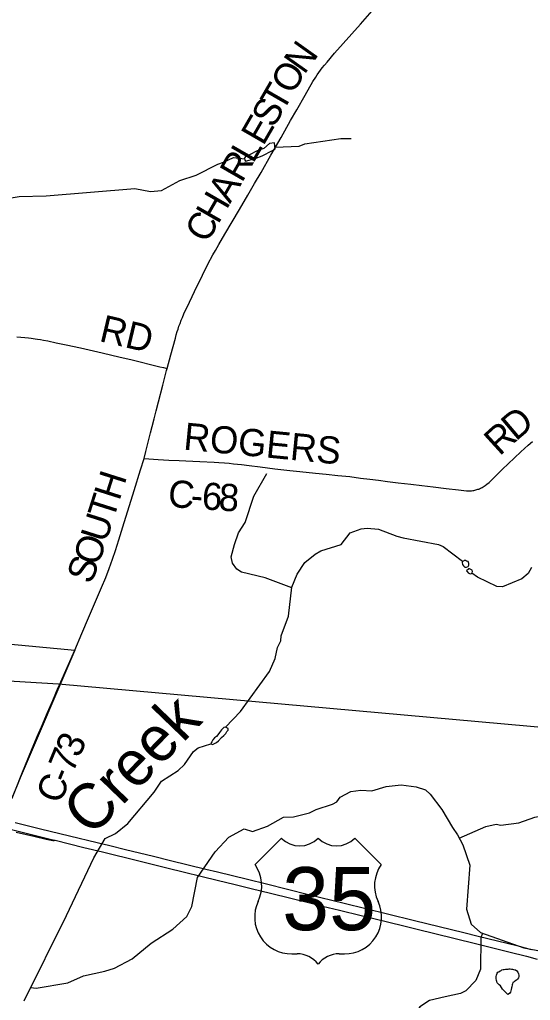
# Model space of a CAD drawing. Extents: x -49 to -8.2, y 9.4 to 23.5.
# Drawn here: x -12.176 to -11.642, y 12.877 to 13.902 of the extents above; entities that cross this region are included whole.
import ezdxf

# ---------------------------------------------------------------- set-up
doc = ezdxf.new("R2010")
doc.units = 0
for name, color, linetype in [('GM_X_Corporation', 7, 'Continuous'), ('GM_X_County_Road', 7, 'Continuous'), ('GM_X_County_Road_Text', 7, 'Continuous'), ('GM_X_Interchange_Ramps', 7, 'Continuous'), ('GM_X_Major_River', 7, 'Continuous'), ('GM_X_Major_River_Text', 7, 'Continuous'), ('GM_X_Minor_Lake', 7, 'Continuous'), ('GM_X_Minor_River', 7, 'Continuous'), ('GM_X_Township', 7, 'Continuous'), ('GM_X_Township_Road', 7, 'Continuous'), ('GM_X_Township_Road_Text', 7, 'Continuous'), ('GM_X_US_Route', 7, 'Continuous'), ('GM_X_US_Shield', 7, 'Continuous')]:
    doc.layers.add(name, color=color, linetype=linetype)

msp = doc.modelspace()

# ---------------------------------------------------------------- linework, layer by layer
at = {"layer": 'GM_X_Corporation'}
msp.add_lwpolyline([(-12.3034, 13.2604), (-12.1182, 13.2429), (-12.1752, 13.1093), (-12.1838, 13.0878)], dxfattribs=at)
at = {"layer": 'GM_X_County_Road'}
for points in [[(-12.0216, 13.5374), (-12.0178, 13.5517), (-12.013, 13.5691), (-12.012, 13.5726), (-12.011, 13.576), (-12.0102, 13.5787), (-12.0092, 13.5816), (-12.0081, 13.5846), (-12.0069, 13.5878), (-12.0056, 13.5909), (-12.0041, 13.5944), (-12.0027, 13.5977), (-12.0007, 13.6017), (-11.9929, 13.618), (-11.9846, 13.635), (-11.9789, 13.6464), (-11.9737, 13.6563), (-11.9711, 13.6608), (-11.9676, 13.6671), (-11.9612, 13.6778), (-11.9536, 13.6906), (-11.9461, 13.7035), (-11.9373, 13.7185), (-11.9302, 13.7309), (-11.9234, 13.7424), (-11.9131, 13.7605), (-11.9025, 13.7791), (-11.8925, 13.7967), (-11.886, 13.808), (-11.8774, 13.8231), (-11.8692, 13.8374), (-11.8663, 13.8422), (-11.8647, 13.8446), (-11.8631, 13.8468), (-11.8613, 13.8492), (-11.8594, 13.8518), (-11.8571, 13.8546), (-11.8544, 13.8578), (-11.8465, 13.867), (-11.8196, 13.8975), (-11.7876, 13.9339)], [(-12.0457, 13.4434), (-12.0439, 13.4505), (-12.0388, 13.4703), (-12.0371, 13.4767), (-12.035, 13.4849), (-12.0329, 13.493), (-12.0305, 13.5025), (-12.0261, 13.52), (-12.0222, 13.5352), (-12.0216, 13.5374)], [(-12.0457, 13.4434), (-12.0308, 13.4423), (-12.0197, 13.4417), (-12.009, 13.4412), (-12.0019, 13.4408), (-11.9875, 13.4402), (-11.9723, 13.4394), (-11.9674, 13.4391), (-11.9615, 13.4387), (-11.9569, 13.4383), (-11.9522, 13.4378), (-11.9439, 13.4369), (-11.9357, 13.436), (-11.9245, 13.4346), (-11.909, 13.4326), (-11.8932, 13.4307), (-11.8828, 13.4296), (-11.8666, 13.4279), (-11.8554, 13.4268), (-11.8433, 13.4256), (-11.8306, 13.4243), (-11.8193, 13.4229), (-11.8098, 13.4218), (-11.8007, 13.4206), (-11.7912, 13.4194), (-11.7802, 13.418), (-11.7668, 13.4164), (-11.7555, 13.4151), (-11.7436, 13.4136), (-11.73, 13.412), (-11.7169, 13.4105), (-11.7116, 13.4099), (-11.7086, 13.4095), (-11.7062, 13.4094), (-11.7047, 13.4095), (-11.7035, 13.4096), (-11.7021, 13.4098), (-11.7009, 13.41), (-11.6989, 13.4105), (-11.6978, 13.4108), (-11.6967, 13.4111), (-11.6958, 13.4114), (-11.6951, 13.4117), (-11.694, 13.4122), (-11.6931, 13.4126), (-11.6922, 13.4131), (-11.6912, 13.4137), (-11.6903, 13.4143), (-11.6892, 13.4151), (-11.6874, 13.4164), (-11.685, 13.4183), (-11.6834, 13.4198), (-11.6766, 13.4265), (-11.6711, 13.4321), (-11.6651, 13.4378), (-11.6586, 13.4439), (-11.6519, 13.4502), (-11.6443, 13.4572), (-11.6398, 13.4612)], [(-12.1182, 13.2429), (-12.1109, 13.2603), (-12.1038, 13.2768), (-12.0902, 13.3084), (-12.0857, 13.319), (-12.0821, 13.3283), (-12.0786, 13.338), (-12.0756, 13.3471), (-12.0722, 13.3584), (-12.0679, 13.372), (-12.056, 13.4099), (-12.0494, 13.4313), (-12.0457, 13.4434)], [(-12.1354, 13.2037), (-12.1341, 13.2068), (-12.1182, 13.2429)], [(-12.1411, 13.1904), (-12.1354, 13.2037)], [(-12.1838, 13.0878), (-12.1801, 13.0969), (-12.1735, 13.1137), (-12.1627, 13.1401), (-12.1573, 13.1526), (-12.153, 13.1626), (-12.1465, 13.1777), (-12.1411, 13.1904)]]:
    msp.add_lwpolyline(points, dxfattribs=at)
at = {"layer": 'GM_X_Interchange_Ramps'}
msp.add_lwpolyline([(-12.1795, 13.0525), (-12.161, 13.0483), (-12.1481, 13.0454), (-12.1427, 13.0442), (-12.1411, 13.0439), (-12.1403, 13.0438), (-12.1395, 13.0439), (-12.1386, 13.0441)], dxfattribs=at)
at = {"layer": 'GM_X_Major_River'}
for points in [[(-11.9604, 13.1623), (-11.9449, 13.1787), (-11.9147, 13.2204), (-11.9086, 13.2341), (-11.9063, 13.2455), (-11.9027, 13.2526), (-11.9023, 13.2579), (-11.8947, 13.2785), (-11.8912, 13.3088), (-11.8857, 13.3222), (-11.8775, 13.3344), (-11.8667, 13.3431), (-11.8609, 13.3467), (-11.8396, 13.3533), (-11.8301, 13.3657), (-11.8187, 13.3698), (-11.8126, 13.3706), (-11.8005, 13.3694), (-11.7814, 13.3622), (-11.775, 13.3604), (-11.7381, 13.3532), (-11.7332, 13.3512), (-11.7129, 13.336)], [(-11.7129, 13.336), (-11.7132, 13.3345), (-11.7129, 13.3325), (-11.7118, 13.331), (-11.7105, 13.3298), (-11.7088, 13.3298), (-11.7069, 13.3305), (-11.7061, 13.3318), (-11.7063, 13.3335), (-11.707, 13.3355), (-11.7085, 13.3361), (-11.7096, 13.3365), (-11.711, 13.3365), (-11.7113, 13.3363)], [(-11.7129, 13.336), (-11.7113, 13.3363)], [(-11.7085, 13.3258), (-11.708, 13.325), (-11.7069, 13.3237), (-11.7056, 13.3229), (-11.7044, 13.3227), (-11.7035, 13.323), (-11.7029, 13.3236), (-11.7023, 13.3253), (-11.7026, 13.3266), (-11.7041, 13.3274), (-11.7056, 13.328), (-11.7064, 13.3279)], [(-11.7064, 13.3279), (-11.7085, 13.3258)], [(-11.6407, 13.3294), (-11.6443, 13.3232), (-11.651, 13.3176), (-11.671, 13.3091), (-11.6769, 13.3096), (-11.6973, 13.3193), (-11.703, 13.3235)], [(-11.9604, 13.1623), (-11.9624, 13.1621), (-11.9648, 13.1597), (-11.9669, 13.1569), (-11.9686, 13.1543), (-11.97, 13.1526), (-11.9719, 13.1511), (-11.9739, 13.1491), (-11.975, 13.1472), (-11.9756, 13.1461), (-11.976, 13.1451), (-11.9743, 13.1443), (-11.9701, 13.1465), (-11.968, 13.148), (-11.9649, 13.1516), (-11.9624, 13.1536), (-11.9603, 13.1558), (-11.9591, 13.1577), (-11.9578, 13.1592), (-11.9579, 13.1611)], [(-11.9579, 13.1611), (-11.9604, 13.1623)], [(-12.1711, 12.8763), (-12.1266, 12.9654), (-12.0981, 13.0259), (-12.0862, 13.0458), (-12.0757, 13.0511), (-12.0626, 13.0618), (-12.0353, 13.0943), (-12.0273, 13.1059), (-12.0099, 13.1171), (-12.0035, 13.1235), (-11.994, 13.137), (-11.989, 13.1406), (-11.9758, 13.145)]]:
    msp.add_lwpolyline(points, dxfattribs=at)
at = {"layer": 'GM_X_Minor_Lake'}
for points in [[(-11.9398, 13.7543), (-11.9295, 13.757), (-11.9223, 13.7597), (-11.9116, 13.7652), (-11.9085, 13.7672), (-11.9094, 13.7733), (-11.9147, 13.7727), (-11.9205, 13.7673), (-11.9273, 13.7649), (-11.9355, 13.7609), (-11.9397, 13.7589)], [(-11.9397, 13.7589), (-11.9404, 13.7582), (-11.9407, 13.7571), (-11.9405, 13.7553), (-11.9398, 13.7543)], [(-11.9604, 13.1623), (-11.9449, 13.1787), (-11.9147, 13.2204), (-11.9086, 13.2341), (-11.9063, 13.2455), (-11.9027, 13.2526), (-11.9023, 13.2579), (-11.8947, 13.2785), (-11.8912, 13.3088), (-11.8857, 13.3222), (-11.8775, 13.3344), (-11.8667, 13.3431), (-11.8609, 13.3467), (-11.8396, 13.3533), (-11.8301, 13.3657), (-11.8187, 13.3698), (-11.8126, 13.3706), (-11.8005, 13.3694), (-11.7814, 13.3622), (-11.775, 13.3604), (-11.7381, 13.3532), (-11.7332, 13.3512), (-11.7129, 13.336)], [(-11.6654, 12.883), (-11.6711, 12.8885), (-11.6733, 12.892), (-11.6744, 12.8931), (-11.6754, 12.8939), (-11.6765, 12.8952), (-11.6769, 12.8964), (-11.6772, 12.8973), (-11.6776, 12.8994), (-11.6776, 12.9008), (-11.6776, 12.9017), (-11.6774, 12.903), (-11.6766, 12.9051), (-11.6758, 12.9061), (-11.6749, 12.9066), (-11.6735, 12.9076), (-11.6726, 12.9081), (-11.6716, 12.9085), (-11.6703, 12.9089), (-11.6692, 12.909), (-11.668, 12.9092), (-11.6667, 12.9092), (-11.665, 12.9094), (-11.664, 12.9095), (-11.6629, 12.9095), (-11.6617, 12.9093), (-11.6606, 12.9093), (-11.6597, 12.9091), (-11.6583, 12.9087), (-11.6574, 12.9085), (-11.6561, 12.9076), (-11.655, 12.9062), (-11.6544, 12.9043), (-11.6538, 12.903), (-11.6539, 12.9016), (-11.6544, 12.9003), (-11.6554, 12.8988), (-11.6564, 12.8979), (-11.6581, 12.8967), (-11.659, 12.896), (-11.6602, 12.8954), (-11.6606, 12.8941), (-11.661, 12.8928), (-11.6614, 12.8907), (-11.6616, 12.8898), (-11.662, 12.888), (-11.6624, 12.8867), (-11.6628, 12.8852), (-11.6635, 12.8841), (-11.6647, 12.8831), (-11.6654, 12.883)]]:
    msp.add_lwpolyline(points, dxfattribs=at)
at = {"layer": 'GM_X_Minor_River'}
for points in [[(-11.9087, 13.7687), (-11.8835, 13.77), (-11.8776, 13.7722), (-11.8401, 13.778), (-11.8293, 13.7779)], [(-12.4055, 13.629), (-12.3833, 13.6343), (-12.3324, 13.6596), (-12.3198, 13.6639), (-12.2664, 13.6757), (-12.2323, 13.6945), (-12.2103, 13.7074), (-12.1948, 13.7141), (-12.1764, 13.7174), (-12.1481, 13.718), (-12.0554, 13.7256), (-12.0389, 13.7225), (-12.0273, 13.7236), (-12.0082, 13.7339), (-11.9914, 13.7397), (-11.9685, 13.7512), (-11.9626, 13.7532), (-11.9521, 13.7581), (-11.9407, 13.7568)], [(-11.8913, 13.3082), (-11.9192, 13.3186), (-11.9439, 13.3243), (-11.9488, 13.3277), (-11.9532, 13.3338), (-11.9548, 13.3403), (-11.9513, 13.3532), (-11.9471, 13.3654), (-11.9399, 13.3763), (-11.9311, 13.4039), (-11.9172, 13.4276)], [(-12.1642, 12.8902), (-12.1584, 12.8893), (-12.1255, 12.8951), (-12.1091, 12.9024), (-12.0866, 12.9071), (-12.0765, 12.9102), (-12.0583, 12.9203), (-12.0383, 12.9365), (-12.0157, 12.9512), (-12.0011, 12.9645), (-11.9956, 12.9748), (-11.9898, 13.0051), (-11.9713, 13.0319), (-11.9572, 13.0472), (-11.9409, 13.0559), (-11.9324, 13.0534), (-11.9166, 13.0588), (-11.8999, 13.0684), (-11.8895, 13.0686), (-11.8728, 13.0729), (-11.8659, 13.0763), (-11.8489, 13.0817), (-11.8441, 13.0843), (-11.8406, 13.0892), (-11.8297, 13.0951), (-11.8191, 13.0964), (-11.8077, 13.0958), (-11.7925, 13.1005), (-11.7769, 13.1019), (-11.7613, 13.0999), (-11.7515, 13.0967), (-11.7466, 13.0924), (-11.7346, 13.0764), (-11.7232, 13.0574), (-11.7182, 13.0499), (-11.7125, 13.0392), (-11.7051, 13.018), (-11.7086, 12.9719), (-11.7039, 12.9564), (-11.6942, 12.9477), (-11.6487, 12.9315), (-11.6286, 12.9279)], [(-11.7163, 13.0464), (-11.6885, 13.0585), (-11.6776, 13.061), (-11.6727, 13.0599), (-11.6539, 13.0624), (-11.6371, 13.0682), (-11.6269, 13.0705), (-11.6125, 13.0702), (-11.5974, 13.065), (-11.5923, 13.0649), (-11.5658, 13.0534), (-11.555, 13.0525), (-11.5396, 13.0526), (-11.5347, 13.054), (-11.508, 13.0518)], [(-11.6921, 12.9469), (-11.6936, 12.942), (-11.694, 12.9093), (-11.6989, 12.8976), (-11.7092, 12.8868), (-11.7149, 12.884), (-11.7311, 12.8804), (-11.7474, 12.8765), (-11.7574, 12.87), (-11.7825, 12.8346)]]:
    msp.add_lwpolyline(points, dxfattribs=at)
at = {"layer": 'GM_X_Township'}
for p, q in [((-12.3691, 13.2212), (-12.1351, 13.2078)), ((-12.1351, 13.2078), (-11.3819, 13.1401))]:
    msp.add_line(p, q, dxfattribs=at)
at = {"layer": 'GM_X_Township_Road'}
msp.add_lwpolyline([(-12.1786, 13.5706), (-12.1703, 13.5697), (-12.1666, 13.5693), (-12.1638, 13.569), (-12.1595, 13.5684), (-12.157, 13.568), (-12.1539, 13.5676), (-12.1508, 13.567), (-12.1463, 13.5662), (-12.1374, 13.5643), (-12.1271, 13.5622), (-12.1122, 13.5589), (-12.0895, 13.5537), (-12.0708, 13.5494), (-12.0596, 13.5467), (-12.0292, 13.5393), (-12.0253, 13.5383), (-12.0216, 13.5374)], dxfattribs=at)
at = {"layer": 'GM_X_US_Route'}
for points in [[(-12.1953, 13.058), (-12.1423, 13.045), (-12.1386, 13.0441), (-12.1085, 13.0367), (-12.0892, 13.0319), (-12.0512, 13.0225), (-12.022, 13.0153), (-11.968, 13.0021), (-11.952, 12.9981), (-11.9336, 12.9935), (-11.9137, 12.9887), (-11.8922, 12.9835), (-11.8696, 12.9779), (-11.8591, 12.9753), (-11.8413, 12.9709), (-11.8189, 12.9655), (-11.8084, 12.963), (-11.7728, 12.9542), (-11.7601, 12.951), (-11.7218, 12.9417), (-11.6979, 12.9358), (-11.6645, 12.9276), (-11.6461, 12.9229), (-11.6347, 12.9198)], [(-12.1804, 13.0626), (-12.1719, 13.0606), (-12.154, 13.0561), (-12.1236, 13.0489), (-12.0946, 13.0418), (-12.0816, 13.0386), (-12.065, 13.0346), (-12.0358, 13.0274), (-12.0182, 13.0231), (-11.9811, 13.014), (-11.9691, 13.011), (-11.9377, 13.0033), (-11.9178, 12.9984), (-11.8737, 12.9875), (-11.8366, 12.9785), (-11.7914, 12.9673), (-11.763, 12.9603), (-11.7114, 12.9477), (-11.6963, 12.944), (-11.6562, 12.934), (-11.6412, 12.93)]]:
    msp.add_lwpolyline(points, dxfattribs=at)
at = {"layer": 'GM_X_US_Shield'}
for p, q in [((-11.9022, 13.0462), (-11.9297, 13.0187)), ((-11.7978, 13.0187), (-11.8253, 13.0462)), ((-11.8912, 12.9253), (-11.8857, 12.9253)), ((-11.8418, 12.9253), (-11.8363, 12.9253))]:
    msp.add_line(p, q, dxfattribs=at)
for centre, radius, start, end in [((-11.883, 13.0658), 0.0275, 225.573, 314.427), ((-11.8445, 13.0658), 0.0275, 225.573, 314.427), ((-11.9612, 12.9967), 0.0385, 334.5471, 35.0009), ((-11.7663, 12.9967), 0.0385, 144.9991, 205.4529), ((-11.8916, 12.9638), 0.0385, 154.8319, 270.6383), ((-11.8359, 12.9638), 0.0385, 269.3617, 25.1681), ((-11.8857, 12.8979), 0.0275, 36.8699, 90), ((-11.8418, 12.8979), 0.0275, 90, 143.1301)]:
    msp.add_arc(centre, radius, start, end, dxfattribs=at)

# ---------------------------------------------------------------- texts
at = {"layer": 'GM_X_County_Road_Text'}
for s, height, rotation, p in [('N', 0.0284, 54.583, (-11.8782, 13.8439)), ('O', 0.0284, 59.9971, (-11.8903, 13.8228)), ('T', 0.0284, 60.0444, (-11.9009, 13.8044)), ('S', 0.0284, 60.0394, (-11.9105, 13.7878)), ('E', 0.0284, 60.0444, (-11.9211, 13.7694)), ('R', 0.0284, 60.0397, (-11.9434, 13.7308)), ('L', 0.0284, 60.0444, (-11.9317, 13.751)), ('A', 0.0284, 60.0416, (-11.9558, 13.7091)), ('H', 0.0284, 60.0416, (-11.9683, 13.6874)), ('C', 0.0284, 60.0416, (-11.98, 13.6672)), ('D', 0.0284, 40.188, (-11.6571, 13.4608)), ('ROGERS', 0.02841, 354.5149, (-12.0052, 13.4527)), ('R', 0.0284, 42.3635, (-11.6741, 13.4452)), ('H', 0.0284, 72.4106, (-12.0715, 13.3983)), ('C', 0.0284, 354.9625, (-12.0215, 13.393)), ('6', 0.0284, 356.3314, (-11.9859, 13.3902)), ('8', 0.0284, 356.4951, (-11.9683, 13.389)), ('T', 0.0284, 72.4159, (-12.0779, 13.3781)), ('-', 0.0284, 356.307, (-11.9975, 13.3909)), ('U', 0.0284, 72.4, (-12.0855, 13.3542)), ('O', 0.0284, 71.4026, (-12.0936, 13.33)), ('S', 0.0284, 68.6203, (-12.1011, 13.3108)), ('3', 0.0284, 66.513, (-12.1135, 13.1293)), ('7', 0.0284, 67.5579, (-12.1202, 13.1133)), ('-', 0.0284, 67.8101, (-12.1246, 13.1025)), ('C', 0.0284, 67.8833, (-12.1333, 13.0809))]:
    msp.add_text(s, height=height, rotation=rotation, dxfattribs=at).set_placement(p)
at = {"layer": 'GM_X_Major_River_Text'}
msp.add_text('Creek', height=0.04736, rotation=46.0163, dxfattribs=at).set_placement((-12.1006, 13.0465))
at = {"layer": 'GM_X_Township_Road_Text'}
msp.add_text('RD', height=0.02841, rotation=346.6748, dxfattribs=at).set_placement((-12.0936, 13.5662))
at = {"layer": 'GM_X_US_Shield'}
msp.add_text('35', height=0.06592, dxfattribs=at).set_placement((-11.9013, 12.9501))

doc.saveas('drawing.dxf')
